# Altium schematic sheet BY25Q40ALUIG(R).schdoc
size 127 x 101 mm
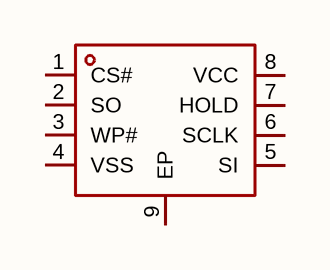
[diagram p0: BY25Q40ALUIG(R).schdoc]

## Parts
U?  by25q40aluig(r)  [USON-8_L3.0-W2.0-P0.50-BL-EP_P25XX]  (value not drawn)

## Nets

Not connected (* = marked no-connect by the designer): U? 1(CS#) 2(SO) 3(WP#) 4(VSS) 5(SI) 6(SCLK) 7(HOLD) 8(VCC) 9(EP)

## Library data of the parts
U? = by25q40aluig(r): 接口类型:SPI;存储容量:4Mbit;时钟频率(fc):85MHz;; Manufacturer: BOYAMICRO(博雅); AddInBom: yes; ModelId: 12a239e5c7384371915ecb51201bf581; ModelName: USON-8_L3.0-W2.0-H0.6-P0.50; ModelTransform: 118.8974,78.74,0,90,0,0,0,0,0; Interface: SPI; Memory Size: 4Mbit; Clock Frequency: 85MHz; Voltage - Supply: 1.65V~2V; Standby Supply Current: 0.6uA; Program / Erase Cycles: 100000次; Page Programming Time (Tpp): 2ms; Data Retention - TDR (Year): 20年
